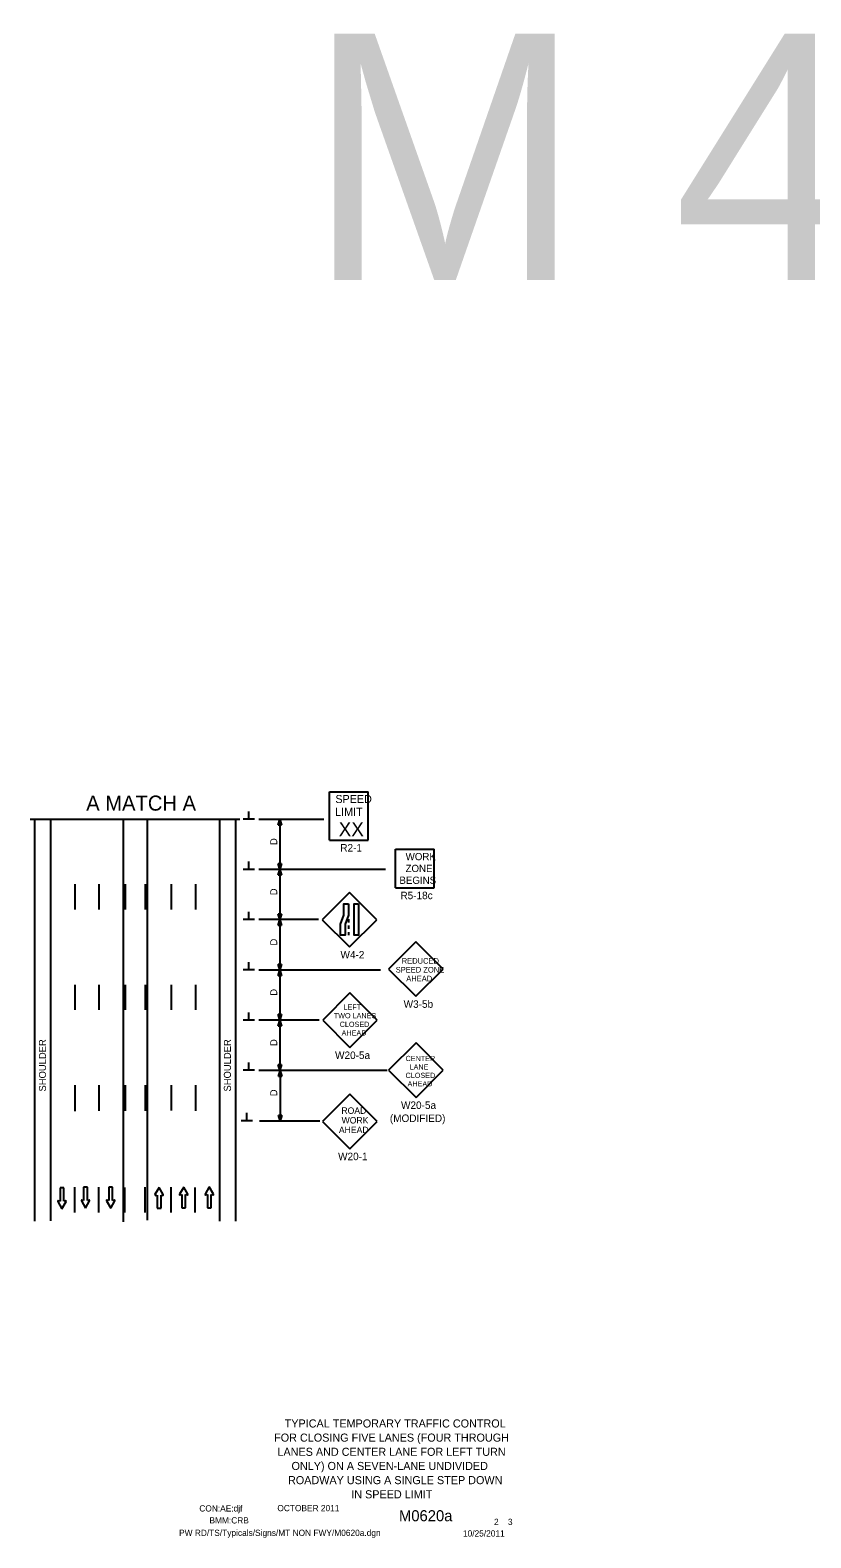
# Model space of a CAD drawing. Extents: x 20837 to 23689, y 414 to 2167.
# Drawn here: x 22136 to 22912, y 667 to 2167 of the extents above; entities that cross this region are included whole.
import ezdxf

# ---------------------------------------------------------------- set-up
doc = ezdxf.new("R2010")
doc.units = 0
for name, color, linetype in [('ALI_LEGAL_EX', 7, 'Continuous'), ('BORDER', 7, 'Continuous'), ('BORDER_SIGNAL_WO', 7, 'Continuous'), ('MT_SCRATCH_LEVEL_E', 7, 'Continuous'), ('PAVT_EDGE_EX', 7, 'Continuous'), ('TRAFFIC_SIGNS_PR', 7, 'Continuous'), ('TYPICAL_TEXT_DIMEN_PR', 7, 'Continuous')]:
    doc.layers.add(name, color=color, linetype=linetype)

msp = doc.modelspace()

# ---------------------------------------------------------------- linework, layer by layer
at = {"layer": 'ALI_LEGAL_EX'}
for points in [[(22180.1, 1317.4), (22180.1, 1292.4)], [(22204.1, 1317.4), (22204.1, 1292.4)], [(22230.1, 1317.4), (22230.1, 1292.4)], [(22250.1, 1317.4), (22250.1, 1292.4)], [(22276.1, 1317.4), (22276.1, 1292.4)], [(22300.1, 1317.4), (22300.1, 1292.4)], [(22180.1, 1217.4), (22180.1, 1192.4)], [(22204.1, 1217.4), (22204.1, 1192.4)], [(22230.1, 1217.4), (22230.1, 1192.4)], [(22250.1, 1217.4), (22250.1, 1192.4)], [(22276.1, 1217.4), (22276.1, 1192.4)], [(22300.1, 1217.4), (22300.1, 1192.4)], [(22180.1, 1117.4), (22180.1, 1091.6)], [(22204.1, 1117.4), (22204.1, 1091.9)], [(22230.1, 1117.4), (22230.1, 1091.9)], [(22250.1, 1117.4), (22250.1, 1091.9)], [(22276.1, 1117.4), (22276.1, 1092.2)], [(22300.1, 1117.4), (22300.1, 1091.9)], [(22180.1, 990.9), (22180.1, 1016)], [(22204, 990.9), (22204, 1016)], [(22229.9, 990.7), (22229.9, 1015.8)], [(22250.2, 990.9), (22250.2, 1016)], [(22276, 990.9), (22276, 1016)], [(22300, 990.7), (22300, 1015.8)]]:
    msp.add_lwpolyline(points, dxfattribs=at)
at = {"layer": 'BORDER'}
msp.add_line((22502.6, 746.5), (22502.6, 746.5), dxfattribs=at)
at = {"layer": 'BORDER_SIGNAL_WO'}
msp.add_line((22502.6, 740.2), (22502.6, 740.2), dxfattribs=at)
at = {"layer": 'MT_SCRATCH_LEVEL_E'}
for p, q in [((22169.2, 1015.4), (22165.5, 1015.4)), ((22165.5, 1015.4), (22165.5, 1002.2)), ((22169.2, 1015.4), (22165.5, 1015.4)), ((22165.5, 1015.4), (22165.5, 1002.2)), ((22169.2, 1002.2), (22169.2, 1015.4)), ((22169.2, 1002.2), (22169.2, 1015.4)), ((22192.7, 1016), (22188.9, 1016)), ((22188.9, 1016), (22188.9, 1002.7)), ((22192.7, 1016), (22188.9, 1016)), ((22188.9, 1016), (22188.9, 1002.7)), ((22192.7, 1002.7), (22192.7, 1016)), ((22192.7, 1002.7), (22192.7, 1016)), ((22217.8, 1016.1), (22214, 1016.1)), ((22214, 1016.1), (22214, 1002.8)), ((22217.8, 1016.1), (22214, 1016.1)), ((22214, 1016.1), (22214, 1002.8)), ((22217.8, 1002.8), (22217.8, 1016.1)), ((22217.8, 1002.8), (22217.8, 1016.1)), ((22264, 1015.8), (22259.9, 1008.6)), ((22264, 1015.8), (22259.9, 1008.6)), ((22260.4, 1007.9), (22262.1, 1008.2)), ((22260.4, 1007.9), (22262.1, 1008.2)), ((22262.1, 1008.2), (22262.1, 995)), ((22262.1, 1008.2), (22262.1, 995)), ((22268.1, 1008.6), (22264, 1015.8)), ((22268.1, 1008.6), (22264, 1015.8)), ((22265.9, 995), (22265.9, 1008.2)), ((22265.9, 1008.2), (22267.6, 1007.9)), ((22265.9, 995), (22265.9, 1008.2)), ((22265.9, 1008.2), (22267.6, 1007.9)), ((22288.5, 1016.2), (22284.4, 1009)), ((22288.5, 1016.2), (22284.4, 1009)), ((22284.9, 1008.3), (22286.7, 1008.6)), ((22284.9, 1008.3), (22286.7, 1008.6)), ((22286.7, 1008.6), (22286.7, 995.4)), ((22286.7, 1008.6), (22286.7, 995.4)), ((22292.7, 1009), (22288.5, 1016.2)), ((22292.7, 1009), (22288.5, 1016.2)), ((22290.4, 995.4), (22290.4, 1008.6)), ((22290.4, 1008.6), (22292.2, 1008.3)), ((22290.4, 995.4), (22290.4, 1008.6)), ((22290.4, 1008.6), (22292.2, 1008.3)), ((22313.8, 1016.3), (22309.7, 1009.1)), ((22313.8, 1016.3), (22309.7, 1009.1)), ((22310.2, 1008.4), (22312, 1008.7)), ((22310.2, 1008.4), (22312, 1008.7)), ((22312, 1008.7), (22312, 995.4)), ((22312, 1008.7), (22312, 995.4)), ((22318, 1009.1), (22313.8, 1016.3)), ((22318, 1009.1), (22313.8, 1016.3)), ((22315.7, 995.4), (22315.7, 1008.7)), ((22315.7, 1008.7), (22317.5, 1008.4)), ((22315.7, 995.4), (22315.7, 1008.7)), ((22315.7, 1008.7), (22317.5, 1008.4)), ((22163.2, 1001.8), (22167.4, 994.5)), ((22163.2, 1001.8), (22167.4, 994.5)), ((22165.5, 1002.2), (22163.7, 1002.5)), ((22165.5, 1002.2), (22163.7, 1002.5)), ((22167.4, 994.5), (22171.5, 1001.8)), ((22167.4, 994.5), (22171.5, 1001.8)), ((22171, 1002.5), (22169.2, 1002.2)), ((22171, 1002.5), (22169.2, 1002.2)), ((22186.7, 1002.3), (22190.8, 995.1)), ((22186.7, 1002.3), (22190.8, 995.1)), ((22188.9, 1002.7), (22187.1, 1003)), ((22188.9, 1002.7), (22187.1, 1003)), ((22190.8, 995.1), (22194.9, 1002.3)), ((22190.8, 995.1), (22194.9, 1002.3)), ((22194.4, 1003), (22192.7, 1002.7)), ((22194.4, 1003), (22192.7, 1002.7)), ((22211.8, 1002.4), (22215.9, 995.2)), ((22211.8, 1002.4), (22215.9, 995.2)), ((22214, 1002.8), (22212.2, 1003.1)), ((22214, 1002.8), (22212.2, 1003.1)), ((22215.9, 995.2), (22220, 1002.4)), ((22215.9, 995.2), (22220, 1002.4)), ((22219.5, 1003.1), (22217.8, 1002.8)), ((22219.5, 1003.1), (22217.8, 1002.8)), ((22262.1, 995), (22265.9, 995)), ((22262.1, 995), (22265.9, 995)), ((22286.7, 995.4), (22290.4, 995.4)), ((22286.7, 995.4), (22290.4, 995.4)), ((22312, 995.4), (22315.7, 995.4)), ((22312, 995.4), (22315.7, 995.4))]:
    msp.add_line(p, q, dxfattribs=at)
for centre, start, end in [((22260.3, 1008.4), 150.4248, 279.9638), ((22260.3, 1008.4), 150.4248, 279.9638), ((22267.7, 1008.4), 260.0362, 29.7731), ((22267.7, 1008.4), 260.0362, 29.7731), ((22284.8, 1008.8), 150.4248, 279.9638), ((22284.8, 1008.8), 150.4248, 279.9638), ((22292.3, 1008.8), 260.0362, 29.7731), ((22292.3, 1008.8), 260.0362, 29.7731), ((22310.1, 1008.8), 150.4248, 279.9638), ((22310.1, 1008.8), 150.4248, 279.9638), ((22317.6, 1008.8), 260.0362, 29.7731), ((22317.6, 1008.8), 260.0362, 29.7731), ((22163.6, 1002), 80.0362, 209.7731), ((22163.6, 1002), 80.0362, 209.7731), ((22171.1, 1002), 330.4248, 99.9638), ((22171.1, 1002), 330.4248, 99.9638), ((22187.1, 1002.6), 80.0362, 209.7731), ((22187.1, 1002.6), 80.0362, 209.7731), ((22194.5, 1002.6), 330.4248, 99.9638), ((22194.5, 1002.6), 330.4248, 99.9638), ((22212.2, 1002.7), 80.0362, 209.7731), ((22212.2, 1002.7), 80.0362, 209.7731), ((22219.6, 1002.7), 330.4248, 99.9638), ((22219.6, 1002.7), 330.4248, 99.9638)]:
    msp.add_arc(centre, 0.463, start, end, dxfattribs=at)
at = {"layer": 'PAVT_EDGE_EX'}
for p, q in [((22140.1, 1382.3), (22140.1, 982.1)), ((22156.1, 1382.3), (22156.1, 982.7)), ((22228.1, 1382.3), (22228.1, 981.5)), ((22252.1, 1382.3), (22252.1, 983.2)), ((22324.1, 1382.3), (22324.1, 982.1)), ((22340.1, 1382.3), (22340.1, 982.1))]:
    msp.add_line(p, q, dxfattribs=at)
at = {"layer": 'TRAFFIC_SIGNS_PR'}
for p, q in [((22433.5, 1409.4), (22471.9, 1409.4)), ((22433.5, 1361.4), (22433.5, 1409.4)), ((22471.9, 1361.4), (22471.9, 1409.4)), ((22433.5, 1361.4), (22471.9, 1361.4)), ((22499.2, 1314), (22499.2, 1352.4)), ((22499.2, 1352.4), (22537.6, 1352.4)), ((22537.6, 1314), (22537.6, 1352.4)), ((22453.5, 1309.4), (22426.3, 1282.2)), ((22480.6, 1282.2), (22453.5, 1309.4)), ((22499.2, 1314), (22537.6, 1314)), ((22426.3, 1282.2), (22453.5, 1255.1)), ((22452.2, 1282.7), (22452.2, 1279.5)), ((22452.2, 1276.3), (22452.2, 1273.1)), ((22453.5, 1255.1), (22480.6, 1282.2)), ((22452.2, 1269.9), (22452.2, 1266.7)), ((22519.2, 1260.3), (22492.1, 1233.1)), ((22546.4, 1233.1), (22519.2, 1260.3)), ((22492.1, 1233.1), (22519.2, 1206)), ((22519.2, 1206), (22546.4, 1233.1)), ((22453.8, 1209.3), (22426.7, 1182.2)), ((22481, 1182.2), (22453.8, 1209.3)), ((22426.7, 1182.2), (22453.8, 1155)), ((22453.8, 1155), (22481, 1182.2)), ((22519.5, 1159.7), (22492.3, 1132.5)), ((22546.6, 1132.5), (22519.5, 1159.7)), ((22492.3, 1132.5), (22519.5, 1105.4)), ((22519.5, 1105.4), (22546.6, 1132.5)), ((22453.8, 1108.7), (22426.6, 1081.5)), ((22481, 1081.5), (22453.8, 1108.7)), ((22426.6, 1081.5), (22453.8, 1054.3)), ((22453.8, 1054.3), (22481, 1081.5))]:
    msp.add_line(p, q, dxfattribs=at)
for points in [[(22452.2, 1297.9), (22452.2, 1286.8), (22448.9, 1277.9), (22448.9, 1266.7), (22444.4, 1266.7), (22444.4, 1277.9), (22447.7, 1286.8), (22447.7, 1297.9)], [(22462.4, 1297.9), (22462.4, 1266.7), (22457.9, 1266.7), (22457.9, 1297.9)]]:
    msp.add_lwpolyline(points, close=True, dxfattribs=at)
at = {"layer": 'TYPICAL_TEXT_DIMEN_PR'}
for p, q in [((22135.8, 1382.3), (22344.4, 1382.3)), ((22228.1, 1382.3), (22252.1, 1382.3)), ((22358.8, 1382.3), (22347.6, 1382.3)), ((22353.2, 1382.3), (22353.2, 1390)), ((22363.1, 1382.3), (22427.8, 1382.3)), ((22382.5, 1376.4), (22384.1, 1382.3)), ((22384.1, 1382.3), (22385.6, 1376.4)), ((22384.1, 1382.3), (22384.1, 1332.3)), ((22384.1, 1376.4), (22382.5, 1376.4)), ((22385.6, 1376.4), (22384.1, 1376.4)), ((22353.2, 1332.3), (22353.2, 1340)), ((22384.1, 1332.3), (22382.5, 1338.1)), ((22382.5, 1338.1), (22384.1, 1338.1)), ((22384.1, 1338.1), (22385.6, 1338.1)), ((22385.6, 1338.1), (22384.1, 1332.3)), ((22358.8, 1332.3), (22347.6, 1332.3)), ((22489, 1332.3), (22363.1, 1332.3)), ((22382.5, 1326.4), (22384.1, 1332.3)), ((22384.1, 1326.4), (22382.5, 1326.4)), ((22384.1, 1332.3), (22385.6, 1326.4)), ((22384.1, 1332.3), (22384.1, 1282.3)), ((22385.6, 1326.4), (22384.1, 1326.4)), ((22358.8, 1282.3), (22347.6, 1282.3)), ((22353.2, 1282.3), (22353.2, 1290)), ((22422.4, 1282.3), (22363.1, 1282.3)), ((22384.1, 1282.3), (22382.5, 1288.1)), ((22382.5, 1288.1), (22384.1, 1288.1)), ((22382.5, 1276.4), (22384.1, 1282.3)), ((22384.1, 1276.4), (22382.5, 1276.4)), ((22384.1, 1288.1), (22385.6, 1288.1)), ((22385.6, 1288.1), (22384.1, 1282.3)), ((22384.1, 1282.3), (22385.6, 1276.4)), ((22384.1, 1282.3), (22384.1, 1232.3)), ((22385.6, 1276.4), (22384.1, 1276.4)), ((22358.8, 1232.3), (22347.6, 1232.3)), ((22353.2, 1232.3), (22353.2, 1240)), ((22363.1, 1232.3), (22484.3, 1232.3)), ((22384.1, 1232.3), (22382.5, 1238.1)), ((22382.5, 1238.1), (22384.1, 1238.1)), ((22382.5, 1226.4), (22384.1, 1232.3)), ((22384.1, 1238.1), (22385.6, 1238.1)), ((22385.6, 1238.1), (22384.1, 1232.3)), ((22384.1, 1232.3), (22385.6, 1226.4)), ((22384.1, 1232.3), (22384.1, 1182.3)), ((22384.1, 1226.4), (22382.5, 1226.4)), ((22385.6, 1226.4), (22384.1, 1226.4)), ((22353.2, 1182.3), (22353.2, 1190)), ((22384.1, 1182.3), (22382.5, 1188.1)), ((22382.5, 1188.1), (22384.1, 1188.1)), ((22384.1, 1188.1), (22385.6, 1188.1)), ((22385.6, 1188.1), (22384.1, 1182.3)), ((22358.8, 1182.3), (22347.6, 1182.3)), ((22423.3, 1182.3), (22363.1, 1182.3)), ((22382.5, 1176.4), (22384.1, 1182.3)), ((22384.1, 1176.4), (22382.5, 1176.4)), ((22384.1, 1182.3), (22385.6, 1176.4)), ((22384.1, 1182.3), (22384.1, 1132.3)), ((22385.6, 1176.4), (22384.1, 1176.4)), ((22358.8, 1132.3), (22347.6, 1132.3)), ((22353.2, 1132.3), (22353.2, 1140)), ((22363.1, 1132.3), (22490.8, 1132.3)), ((22384.1, 1132.3), (22382.5, 1138.1)), ((22382.5, 1138.1), (22384.1, 1138.1)), ((22382.8, 1126), (22384.4, 1131.9)), ((22384.4, 1126), (22382.8, 1126)), ((22384.1, 1138.1), (22385.6, 1138.1)), ((22385.6, 1138.1), (22384.1, 1132.3)), ((22384.4, 1131.9), (22384.4, 1081.9)), ((22384.4, 1131.9), (22385.9, 1126)), ((22385.9, 1126), (22384.4, 1126)), ((22356.8, 1082.1), (22345.5, 1082.1)), ((22356.8, 1082.1), (22345.5, 1082.1)), ((22351.1, 1082.1), (22351.1, 1089.9)), ((22351.1, 1082.1), (22351.1, 1089.9)), ((22364, 1081.9), (22423.7, 1081.9)), ((22384.4, 1081.9), (22382.8, 1087.7)), ((22382.8, 1087.7), (22384.4, 1087.7)), ((22384.4, 1081.9), (22382.8, 1087.7)), ((22382.8, 1087.7), (22384.4, 1087.7)), ((22384.4, 1087.7), (22385.9, 1087.7)), ((22385.9, 1087.7), (22384.4, 1081.9)), ((22384.4, 1087.7), (22385.9, 1087.7)), ((22385.9, 1087.7), (22384.4, 1081.9))]:
    msp.add_line(p, q, dxfattribs=at)

# ---------------------------------------------------------------- texts
at = {"layer": 'BORDER_SIGNAL_WO'}
for s, height, p in [('TYPICAL TEMPORARY TRAFFIC CONTROL', 8.039, (22388.9, 776.9)), ('FOR CLOSING FIVE LANES (FOUR THROUGH', 8.039, (22378.4, 762.8)), ('LANES AND CENTER LANE FOR LEFT TURN', 8.039, (22381.7, 748.7)), ('ONLY) ON A SEVEN-LANE UNDIVIDED', 8.039, (22395.7, 734.6)), ('ROADWAY USING A SINGLE STEP DOWN', 8.039, (22392.2, 720.5)), ('IN SPEED LIMIT', 8.039, (22455.1, 706.4)), ('CON:AE:djf', 6.2, (22304, 693.3)), ('    OCTOBER 2011    ', 6.2, (22372.4, 693.6)), ('    M0620a   ', 11, (22486.2, 683.6)), ('PW RD/TS/Typicals/Signs/MT NON FWY/M0620a.dgn    ', 6.2, (22283.9, 669)), ('BMM:CRB   ', 6.2, (22314.1, 681.4)), (' 2    3 ', 6.2, (22594.8, 679.9)), ('10/25/2011    ', 6.2, (22566.2, 668.4))]:
    msp.add_text(s, height=height, dxfattribs=at).set_placement(p)
at = {"layer": 'TRAFFIC_SIGNS_PR'}
for s, height, p in [('SPEED', 8, (22439.3, 1398.3)), ('LIMIT', 8, (22439.1, 1385.5)), ('XX', 14.03, (22442.6, 1365.2)), ('R2-1', 7.44, (22444.2, 1350)), ('WORK', 7.22, (22509.2, 1341.4)), ('ZONE', 7.22, (22509.1, 1329.6)), ('BEGINS', 7.22, (22503, 1317.8)), ('R5-18c', 7.44, (22504, 1302.6)), ('W4-2', 7.44, (22444.4, 1243.6)), ('SPEED ZONE', 5.6, (22499.3, 1229.6)), ('REDUCED', 5.6, (22505.3, 1238.4)), ('AHEAD', 5.6, (22509.8, 1220.8)), ('W3-5b', 7.44, (22507.2, 1194.5)), ('TWO LANES', 5.2, (22437.7, 1184.1)), ('LEFT', 5.2, (22447.4, 1192.7)), ('CLOSED', 5.2, (22443.6, 1175.5)), ('AHEAD', 5.2, (22445.5, 1166.9)), ('W20-5a', 7.44, (22439, 1143.6)), ('CENTER', 5.2, (22509.1, 1141.5)), ('CLOSED', 5.2, (22509.1, 1124.7)), ('LANE', 5.2, (22513.1, 1133.1)), ('AHEAD', 5.2, (22511.1, 1116.3)), ('ROAD', 6.41, (22445.3, 1089)), ('W20-5a', 7.44, (22504.6, 1093.9)), ('WORK', 6.41, (22445.5, 1079.4)), ('(MODIFIED)', 7.44, (22493.5, 1080.9)), ('AHEAD', 6.41, (22442.8, 1069.8)), ('W20-1', 7.45, (22442, 1042.9))]:
    msp.add_text(s, height=height, dxfattribs=at).set_placement(p)
at = {"layer": 'TYPICAL_TEXT_DIMEN_PR'}
for s, height, p in [('M 48', 245.04, (22411.4, 1918.7)), ('A MATCH A', 15, (22191.5, 1390.7))]:
    msp.add_text(s, height=height, dxfattribs=at).set_placement(p)
for s, p in [('D', (22381.5, 1356.5)), ('D', (22381.5, 1306.5)), ('D', (22381.5, 1306.5)), ('D', (22381.5, 1256.5)), ('D', (22381.5, 1206.5)), ('SHOULDER', (22151.5, 1111.2)), ('SHOULDER', (22335.4, 1111.2)), ('D', (22381.5, 1156.5)), ('D', (22381.5, 1106.5))]:
    msp.add_text(s, height=7, rotation=90, dxfattribs=at).set_placement(p)

doc.saveas('drawing.dxf')
